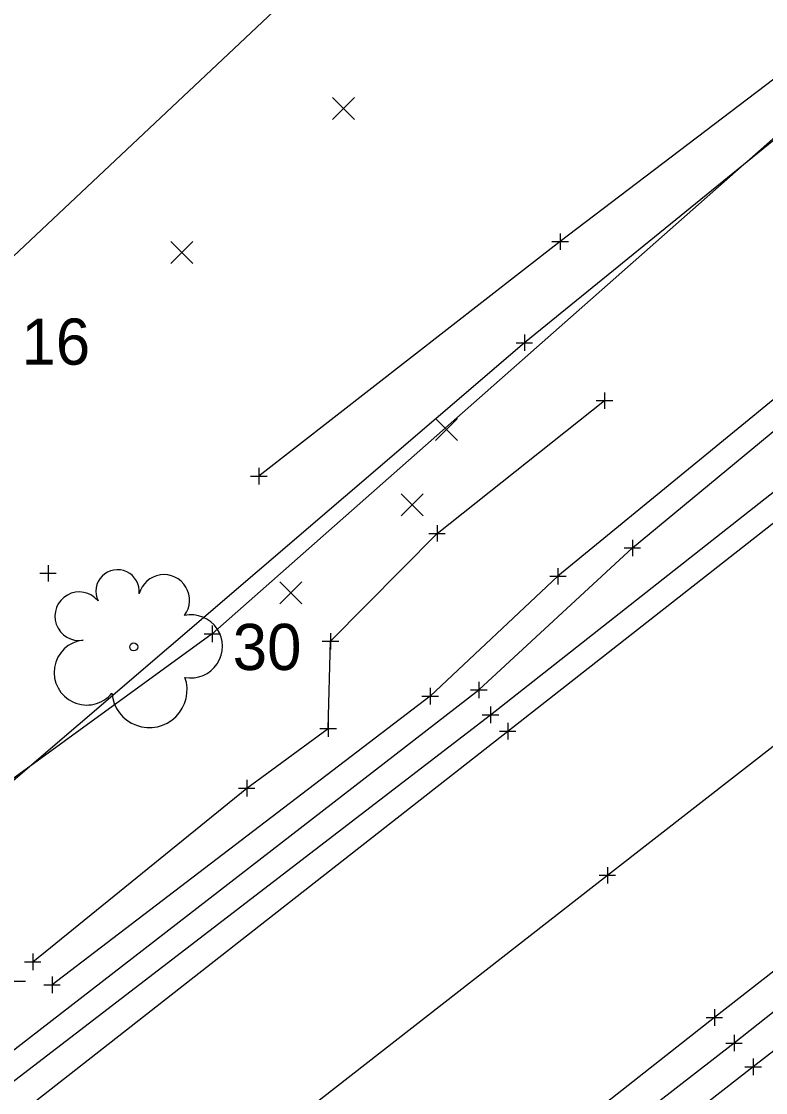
# Model space of a CAD drawing. Extents: x 2184635 to 2185378, y 369880 to 370486.
# Drawn here: x 2184907.9 to 2184953, y 370120.8 to 370185.8 of the extents above; entities that cross this region are included whole.
import ezdxf

# ---------------------------------------------------------------- set-up
doc = ezdxf.new("R2010")
doc.units = 0
for name, color, linetype in [('_CIVIL_CONSTRUCTION', 7, 'Continuous'), ('GE_X_Alignment', 7, 'Continuous'), ('GE_X_Alignment_100_Distances', 7, 'Continuous'), ('PM_X_CL_Pass_Proh_Lt', 7, 'Continuous'), ('PM_X_CL_Pass_Proh_Rt', 7, 'Continuous'), ('PM_X_Edge_Line', 7, 'Continuous'), ('PV_X_COP', 7, 'Continuous'), ('PV_X_EOP', 7, 'Continuous'), ('PV_X_Shoulder', 7, 'Continuous'), ('RD_X_Fence', 7, 'Continuous'), ('RW_X_CL', 7, 'Continuous'), ('SV_X_Break_Lines', 7, 'Continuous'), ('SV_X_Terrain_Boundary', 7, 'Continuous'), ('SV_X_Top_of_Bank', 7, 'Continuous'), ('VG_X_Text', 7, 'Continuous'), ('VG_X_Tree_Line_Lt', 7, 'Continuous')]:
    doc.layers.add(name, color=color, linetype=linetype)

msp = doc.modelspace()

# ---------------------------------------------------------------- linework, layer by layer
at = {"layer": '_CIVIL_CONSTRUCTION'}
for p, q in [((2184926.734, 370179.81), (2184928.067, 370181.145)), ((2184926.734, 370181.145), (2184928.067, 370179.81)), ((2184916.937, 370171.08), (2184918.271, 370172.415)), ((2184916.937, 370172.415), (2184918.271, 370171.08)), ((2184932.99, 370160.351), (2184934.323, 370161.686)), ((2184932.99, 370161.686), (2184934.323, 370160.351)), ((2184930.9, 370155.782), (2184932.233, 370157.117)), ((2184930.9, 370157.117), (2184932.233, 370155.782)), ((2184923.552, 370150.444), (2184924.886, 370151.779)), ((2184923.552, 370151.779), (2184924.886, 370150.444))]:
    msp.add_line(p, q, dxfattribs=at)
at = {"layer": 'GE_X_Alignment'}
msp.add_circle((2184914.688, 370147.839), 0.24, dxfattribs=at)
for centre, radius, start, end in [((2184913.704, 370151.206), 1.317, 354.0047, 205.97412), ((2184916.514, 370150.668), 1.553, 323.82996, 165.0376), ((2184911.378, 370149.703), 1.471, 39.06254, 279.54124), ((2184918.148, 370147.875), 1.915, 259.14531, 101.45961), ((2184911.834, 370146.29), 1.974, 96.17219, 320.57371), ((2184915.634, 370145.233), 2.284, 184.94757, 19.45715)]:
    msp.add_arc(centre, radius, start, end, dxfattribs=at)
at = {"layer": 'GE_X_Alignment_100_Distances'}
for points in [[(2185264.317, 370371.308), (2185225.669, 370339.838), (2185186.917, 370307.744), (2185148.745, 370277.089), (2185109.073, 370245.724), (2185070.468, 370214.753), (2185031.044, 370183.419), (2184991.951, 370153.137), (2184952.243, 370122.384), (2184912.885, 370091.687), (2184876.597, 370062.99), (2184874.528, 370062.204), (2184872.479, 370060.466), (2184871.454, 370058.823), (2184869.46, 370057.791), (2184834.83, 370028.947), (2184796.151, 369998.173), (2184773.728, 369979.618), (2184757.686, 369965.832), (2184717.275, 369935.855), (2184678.357, 369904.181)], [(2184659.612, 369925.949), (2184700.373, 369957.788), (2184738.497, 369988.629), (2184777.827, 370020.252), (2184816.427, 370051.346), (2184855.546, 370082.582), (2184897.005, 370115.363), (2184935.605, 370145.229), (2184944.916, 370153.839), (2184957.869, 370164.566), (2184961.936, 370169.284), (2184974.725, 370179.722), (2184983.893, 370187.218), (2184992.505, 370194.662), (2184997.566, 370200.246)]]:
    msp.add_lwpolyline(points, dxfattribs=at)
at = {"layer": 'PM_X_CL_Pass_Proh_Lt'}
msp.add_lwpolyline([(2185262.142, 370374.202), (2185223.699, 370342.03), (2185185.178, 370310.659), (2185146.677, 370279.544), (2185107.738, 370248.35), (2185068.5, 370216.963), (2185029.051, 370186.04), (2184989.472, 370156.275), (2184949.89, 370125.369), (2184910.765, 370094.563), (2184870.979, 370063.529), (2184832.077, 370032.401), (2184793.204, 370001.486), (2184754.34, 369970.024), (2184715.121, 369938.505), (2184676.144, 369907.221)], dxfattribs=at)
at = {"layer": 'PM_X_CL_Pass_Proh_Rt'}
msp.add_lwpolyline([(2184772.075, 369998.33), (2184786.357, 370009.443), (2184824.962, 370040.257), (2184864.241, 370071.885), (2184905.968, 370104.805), (2184943.399, 370133.995), (2184983.483, 370165.213), (2185020.257, 370194.467), (2185061.224, 370226.635), (2185099.743, 370257.779), (2185139.182, 370289.511), (2185177.352, 370320.307), (2185216.054, 370351.804), (2185254.728, 370383.452)], dxfattribs=at)
at = {"layer": 'PM_X_Edge_Line'}
msp.add_lwpolyline([(2184661.525, 369922.948), (2184702.122, 369955.424), (2184740.459, 369986.306), (2184779.792, 370018.036), (2184818.421, 370048.832), (2184857.458, 370080.192), (2184899.139, 370112.801), (2184937.357, 370142.735), (2184976.78, 370173.64), (2185013.226, 370203.926), (2185054.743, 370235.213), (2185093.131, 370266.204), (2185132.902, 370298.208), (2185170.876, 370328.987), (2185209.713, 370360.437), (2185248.243, 370392.049)], dxfattribs=at)
at = {"layer": 'PV_X_COP'}
msp.add_lwpolyline([(2184667.936, 369914.544), (2184708.437, 369946.755), (2184746.444, 369977.522), (2184786.357, 370009.443), (2184824.962, 370040.257), (2184864.241, 370071.885), (2184905.968, 370104.805), (2184943.399, 370133.995), (2184983.483, 370165.213), (2185020.257, 370194.467), (2185061.224, 370226.635), (2185099.743, 370257.779), (2185139.182, 370289.511), (2185177.352, 370320.307), (2185216.054, 370351.804), (2185254.679, 370383.196)], dxfattribs=at)
at = {"layer": 'PV_X_EOP'}
for points in [[(2184661.562, 369922.858), (2184702.122, 369955.424), (2184740.459, 369986.306), (2184779.792, 370018.036), (2184818.421, 370048.832), (2184857.458, 370080.192), (2184899.139, 370112.801), (2184937.357, 370142.735), (2184976.78, 370173.64), (2185013.226, 370203.926), (2185054.743, 370235.213), (2185093.131, 370266.204), (2185132.902, 370298.208), (2185170.876, 370328.987), (2185209.713, 370360.437), (2185248.181, 370392.045)], [(2185262.152, 370374.256), (2185223.699, 370342.03), (2185185.178, 370310.659), (2185146.677, 370279.544), (2185107.738, 370248.35), (2185068.5, 370216.963), (2185029.051, 370186.04), (2184989.472, 370156.275), (2184949.89, 370125.369), (2184910.765, 370094.563), (2184870.979, 370063.529), (2184832.077, 370032.401), (2184793.204, 370001.486), (2184754.34, 369970.024), (2184715.121, 369938.505), (2184676.223, 369907.131)]]:
    msp.add_lwpolyline(points, dxfattribs=at)
at = {"layer": 'PV_X_Shoulder'}
for points in [[(2184660.616, 369924.653), (2184701.177, 369956.993), (2184739.308, 369987.689), (2184778.66, 370019.08), (2184817.145, 370050.202), (2184856.424, 370081.402), (2184897.962, 370114.276), (2184936.317, 370143.726), (2184975.811, 370174.815), (2184986.608, 370184.308), (2184994.082, 370192.548), (2185011.043, 370206.648), (2185033.171, 370224.287), (2185051.814, 370238.9), (2185062.885, 370246.964), (2185064.956, 370248.001), (2185067.328, 370248.113), (2185092.06, 370267.243), (2185132.002, 370299.513), (2185169.971, 370330.255), (2185208.837, 370361.607), (2185247.242, 370392.983)], [(2185263.127, 370373.08), (2185224.626, 370341.08), (2185185.979, 370309.587), (2185147.251, 370278.484), (2185108.316, 370247.412), (2185069.303, 370216.141), (2185029.865, 370185.151), (2184990.36, 370154.899), (2184951.083, 370123.826), (2184911.784, 370093.315), (2184872.077, 370062.156), (2184833.336, 370030.958), (2184794.18, 369999.967), (2184755.603, 369968.652), (2184716.02, 369937.324), (2184677.487, 369905.633)]]:
    msp.add_lwpolyline(points, dxfattribs=at)
at = {"layer": 'RD_X_Fence'}
msp.add_lwpolyline([(2185015.199, 370283.15), (2185015.458, 370270.123), (2185015.389, 370244.361), (2185014.511, 370228.509), (2185000.874, 370217.983), (2184983.945, 370203.779), (2184965.468, 370188.326), (2184938.367, 370166.286), (2184905.933, 370138.502), (2184906.07, 370146.446), (2184906.533, 370163.609)], dxfattribs=at)
at = {"layer": 'RW_X_CL'}
for p, q in [((2184940.542, 370172.914), (2184940.542, 370171.914)), ((2184940.042, 370172.414), (2184941.042, 370172.414)), ((2184940.542, 370172.414), (2184940.542, 370172.414)), ((2184937.867, 370166.286), (2184938.867, 370166.286)), ((2184938.367, 370166.786), (2184938.367, 370165.786)), ((2184938.367, 370166.286), (2184938.367, 370166.286)), ((2184943.229, 370163.274), (2184943.229, 370162.274)), ((2184942.729, 370162.774), (2184943.729, 370162.774)), ((2184943.229, 370162.774), (2184943.229, 370162.774)), ((2184922.269, 370158.692), (2184922.269, 370157.692)), ((2184921.769, 370158.192), (2184922.769, 370158.192)), ((2184922.269, 370158.192), (2184922.269, 370158.192)), ((2184932.576, 370154.725), (2184933.576, 370154.725)), ((2184933.076, 370155.225), (2184933.076, 370154.225)), ((2184933.076, 370154.725), (2184933.076, 370154.725)), ((2184944.916, 370154.339), (2184944.916, 370153.339)), ((2184944.416, 370153.839), (2184945.416, 370153.839)), ((2184944.916, 370153.839), (2184944.916, 370153.839)), ((2184909.488, 370152.803), (2184909.488, 370151.803)), ((2184908.988, 370152.303), (2184909.988, 370152.303)), ((2184909.488, 370152.303), (2184909.488, 370152.303)), ((2184939.906, 370152.123), (2184940.906, 370152.123)), ((2184940.406, 370152.623), (2184940.406, 370151.623)), ((2184940.406, 370152.123), (2184940.406, 370152.123)), ((2184919.447, 370149.13), (2184919.447, 370148.13)), ((2184918.947, 370148.63), (2184919.947, 370148.63)), ((2184919.447, 370148.63), (2184919.447, 370148.63)), ((2184926.115, 370148.182), (2184927.115, 370148.182)), ((2184926.615, 370148.682), (2184926.615, 370147.682)), ((2184926.615, 370148.182), (2184926.615, 370148.182)), ((2184935.605, 370145.729), (2184935.605, 370144.729)), ((2184932.157, 370144.859), (2184933.157, 370144.859)), ((2184932.657, 370145.359), (2184932.657, 370144.359)), ((2184932.657, 370144.859), (2184932.657, 370144.859)), ((2184935.105, 370145.229), (2184936.105, 370145.229)), ((2184935.605, 370145.229), (2184935.605, 370145.229)), ((2184936.317, 370144.226), (2184936.317, 370143.226)), ((2184935.817, 370143.726), (2184936.817, 370143.726)), ((2184936.317, 370143.726), (2184936.317, 370143.726)), ((2184926.478, 370143.395), (2184926.478, 370142.395)), ((2184937.357, 370143.235), (2184937.357, 370142.235)), ((2184937.357, 370143.235), (2184937.357, 370142.235)), ((2184925.978, 370142.895), (2184926.978, 370142.895)), ((2184926.478, 370142.895), (2184926.478, 370142.895)), ((2184936.857, 370142.735), (2184937.857, 370142.735)), ((2184936.857, 370142.735), (2184937.857, 370142.735)), ((2184937.357, 370142.735), (2184937.357, 370142.735)), ((2184937.357, 370142.735), (2184937.357, 370142.735)), ((2184921.533, 370139.776), (2184921.533, 370138.776)), ((2184921.033, 370139.276), (2184922.033, 370139.276)), ((2184921.533, 370139.276), (2184921.533, 370139.276)), ((2184943.399, 370134.495), (2184943.399, 370133.495)), ((2184943.399, 370134.495), (2184943.399, 370133.495)), ((2184942.899, 370133.995), (2184943.899, 370133.995)), ((2184942.899, 370133.995), (2184943.899, 370133.995)), ((2184943.399, 370133.995), (2184943.399, 370133.995)), ((2184943.399, 370133.995), (2184943.399, 370133.995)), ((2184908.058, 370128.75), (2184909.058, 370128.75)), ((2184908.558, 370129.25), (2184908.558, 370128.25)), ((2184908.558, 370128.75), (2184908.558, 370128.75)), ((2184907.128, 370127.568), (2184908.128, 370127.568)), ((2184909.234, 370127.354), (2184910.234, 370127.354)), ((2184909.734, 370127.854), (2184909.734, 370126.854)), ((2184909.734, 370127.354), (2184909.734, 370127.354)), ((2184949.39, 370125.369), (2184950.39, 370125.369)), ((2184949.39, 370125.369), (2184950.39, 370125.369)), ((2184949.89, 370125.869), (2184949.89, 370124.869)), ((2184949.89, 370125.869), (2184949.89, 370124.869)), ((2184949.89, 370125.369), (2184949.89, 370125.369)), ((2184949.89, 370125.369), (2184949.89, 370125.369)), ((2184951.083, 370124.326), (2184951.083, 370123.326)), ((2184950.583, 370123.826), (2184951.583, 370123.826)), ((2184951.083, 370123.826), (2184951.083, 370123.826)), ((2184952.243, 370122.884), (2184952.243, 370121.884)), ((2184951.743, 370122.384), (2184952.743, 370122.384)), ((2184952.243, 370122.384), (2184952.243, 370122.384))]:
    msp.add_line(p, q, dxfattribs=at)
at = {"layer": 'SV_X_Break_Lines'}
msp.add_line((2184909.488, 370152.303), (2184909.488, 370152.303), dxfattribs=at)
for points in [[(2184981.838, 370244.628), (2184966.756, 370227.412), (2184963.344, 370214.869), (2184959.896, 370189.547), (2184954.002, 370182.636), (2184940.542, 370172.414), (2184922.269, 370158.192)], [(2184908.558, 370128.75), (2184921.533, 370139.276), (2184926.478, 370142.895), (2184926.615, 370148.182), (2184933.076, 370154.725), (2184943.229, 370162.774)]]:
    msp.add_lwpolyline(points, dxfattribs=at)
at = {"layer": 'SV_X_Terrain_Boundary'}
msp.add_lwpolyline([(2185048.788, 370280.746), (2184981.838, 370244.628), (2184966.756, 370227.412), (2184901.88, 370166.351), (2184859.946, 370200.015), (2184846.285, 370205.144), (2184825.044, 370216.074), (2184786.251, 370161.278), (2184768.884, 370142.96), (2184755.889, 370127.052), (2184768.662, 370083.987), (2184723.55, 370028.868), (2184709.399, 370017.08), (2184650.834, 369961.553), (2184636.069, 369950.037)], dxfattribs=at)
at = {"layer": 'SV_X_Top_of_Bank'}
msp.add_lwpolyline([(2184975.144, 370182.101), (2184956.454, 370165.28), (2184940.406, 370152.123), (2184932.657, 370144.859), (2184909.734, 370127.354)], dxfattribs=at)
at = {"layer": 'VG_X_Tree_Line_Lt'}
msp.add_lwpolyline([(2185010.677, 370261.152), (2185009.496, 370230.83), (2184994.447, 370214.873), (2184919.447, 370148.63), (2184883.31, 370122.364), (2184845.078, 370084.673), (2184789.476, 370110.598), (2184762.675, 370135.815)], dxfattribs=at)

# ---------------------------------------------------------------- texts
at = {"layer": 'VG_X_Text'}
for s, p in [('16', (2184907.88, 370164.95)), ('30', (2184920.688, 370146.439))]:
    msp.add_text(s, height=2.8, dxfattribs=at).set_placement(p)

doc.saveas('drawing.dxf')
